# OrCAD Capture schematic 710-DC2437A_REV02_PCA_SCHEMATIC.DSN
size Custom; note: 45V VIN, 500mA LOW NOISE LINEAR REGULATOR WITH; note: PROGRAMMABLE CURRENT LIMIT AND OUTPUT DISCHARGE
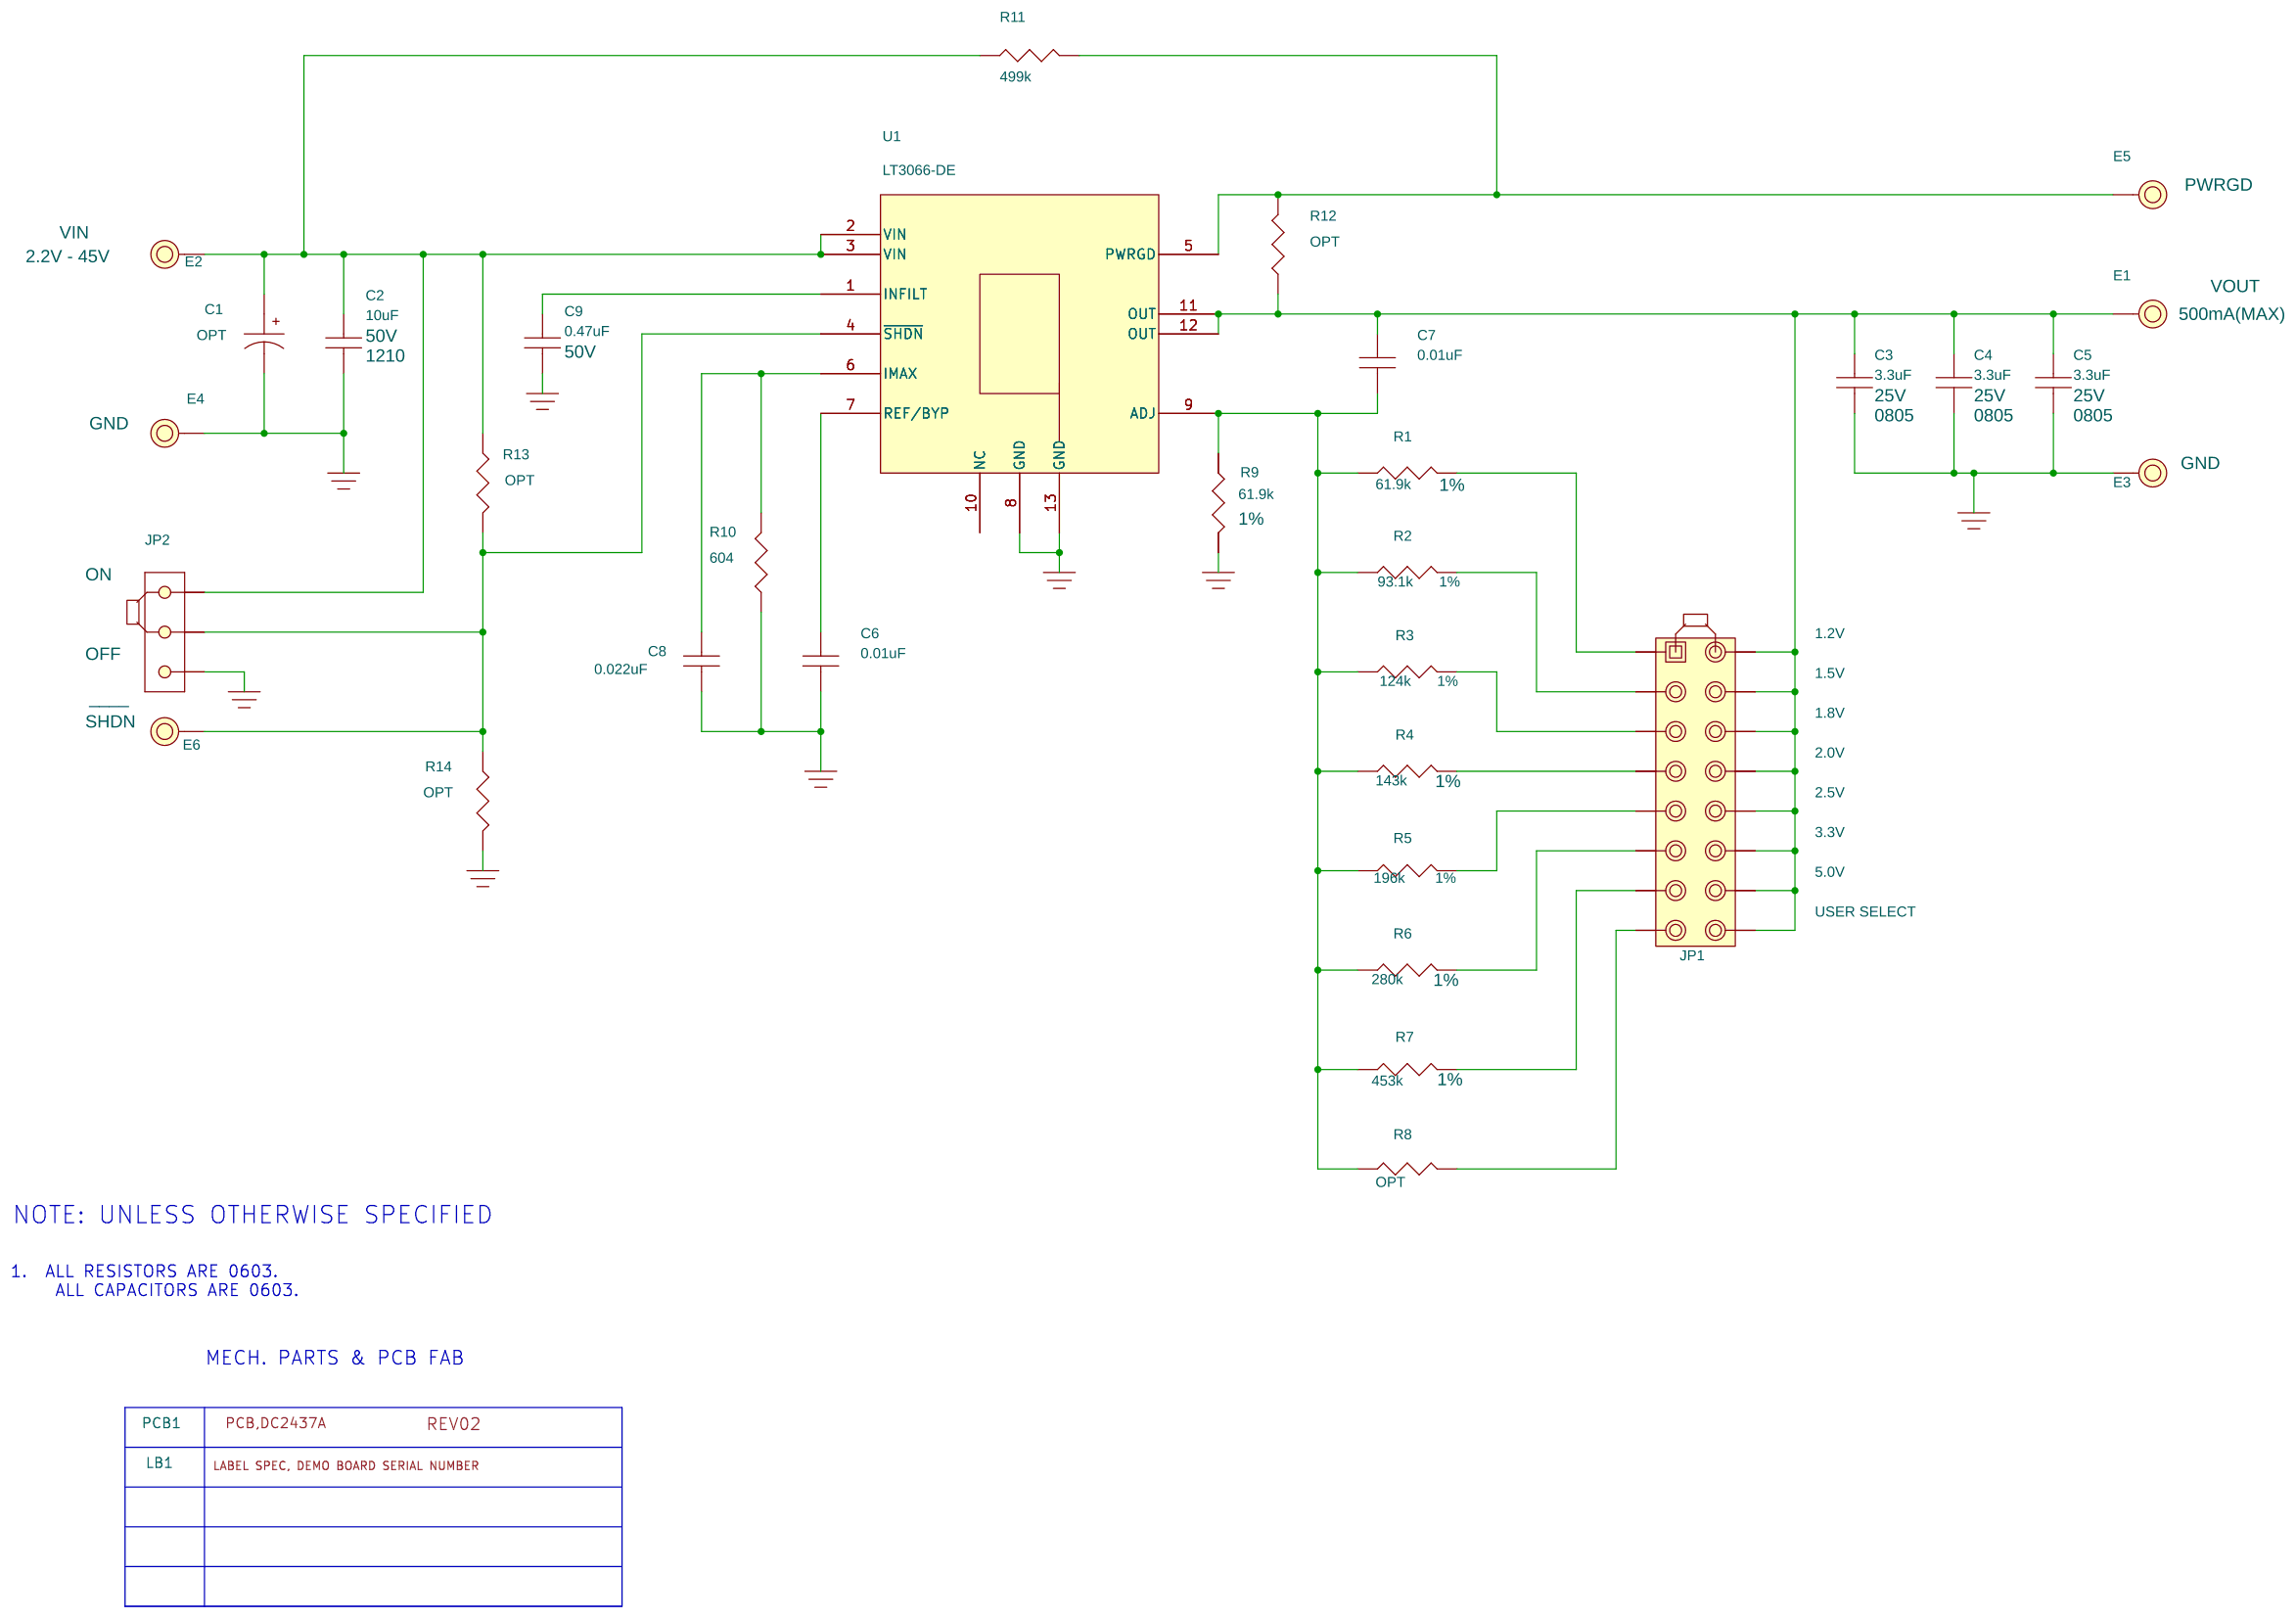
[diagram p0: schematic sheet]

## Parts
C1  OPT  [SUNCON-6.3X5.4]
C2  10uF  [CC1210N]
C3  3.3uF  [CC0805N]
C4  3.3uF  [CC0805N]
C5  3.3uF  [CC0805N]
C6  0.01uF  [CC0603N]
C7  0.01uF  [CC0603N]
C8  0.022uF  [CC0603N]
C9  0.47uF  [CC0603N]
E1  TEST POINT  [MILLMAX2501]
E2  TEST POINT  [MILLMAX2501]
E3  TEST POINT  [MILLMAX2501]
E4  TEST POINT  [MILLMAX2501]
E5  TEST POINT  [MILLMAX2501]
E6  TEST POINT  [MILLMAX2501]
JP1  HEADER  [HD2X8-079]
JP2  HEADER  [JP3X1/079]
LB1  LABEL  [895-0154_REV01]
PCB1  PCB,DC2437A  [MECHANICAL_PART]
R1  61.9k  [CR0603N]
R2  93.1k  [CR0603N]
R3  124k  [CR0603N]
R4  143k  [CR0603N]
R5  196k  [CR0603N]
R6  280k  [CR0603N]
R7  453k  [CR0603N]
R8  OPT  [CR0603N]
R9  61.9k  [CR0603N]
R10  604  [CR0603N]
R11  499k  [CR0603N]
R12  OPT  [CR0603N]
R13  OPT  [CR0603N]
R14  OPT  [CR0603N]
U1  LT3066-DE  [LTC-DE/UE]
XJP1  SHUNT
XJP2  SHUNT

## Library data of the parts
C1 = CAP_P: CAP., OPTION, ALUM. ELECT., SMD; CLASS: DISCRETE; Dielectric Type: ALUM. ELECTROLYTIC; FPLIST: CAP-HVH-6.3X4.5,SUNCON-8X10.2,SUNCON-6.3X5.4; PART_NUMBER: OPT-0011; Package Size: SMT
C2 = CAP: CAP.,10uF,X7R,50V,10%,1210; CLASS: DISCRETE; Dielectric Type: X7R; Manufacturer: MURATA; Manufacturer PN: GRM32ER71H106KA12L; PART_NUMBER: 150-3043; Package Size: 1210; Rated Voltage: 50V; Tolerance: 10%
C3-C5 = CAP: CAP.,3.3uF,X7R,25V,10%,0805; CLASS: DISCRETE; Dielectric Type: X7R; Manufacturer: MURATA; Manufacturer PN: GRM21BR71E335KA73L; PART_NUMBER: 150-0373; Package Size: 0805; Rated Voltage: 25V; Temperature Coefficient: X7R; Tolerance: 10%
C6 C7 = CAP: CAP.,0.01uF,X7R,16V,10%,0603; CLASS: DISCRETE; Dielectric Type: X7R; FPLIST: CC0603N,CC0603L,CC0603M; Manufacturer: AVX; Manufacturer PN: 0603YC103KAT2A; PART_NUMBER: 150-0038; Package Size: 0603; Rated Voltage: 16V; Tolerance: 10%
C8 = CAP: CAP.,0.022uF,X7R,16V,10%,0603; CLASS: DISCRETE; Dielectric Type: X7R; FPLIST: CC0603N,CC0603L,CC0603M; Manufacturer: MURATA; Manufacturer PN: GRM188R71C223KA01D; PART_NUMBER: 150-3074; Package Size: 0603; Rated Voltage: 16V; Tolerance: 10%
C9 = CAP: CAP.,0.47uF,X7R,50V,10%,0603; CLASS: DISCRETE; Dielectric Type: X7R; Manufacturer: TDK; Manufacturer PN: C1608X7R1H474K080AC; PART_NUMBER: 150-0374; Package Size: 0603; Rated Voltage: 50V; Temperature Coefficient: X7R; Tolerance: 10%
E1 = TESTPOINT_.219_MILL-MAX_2501: TEST POINT,TURRET,0.094",MTG. HOLE; CLASS: IO; Manufacturer: MILL-MAX; Manufacturer PN: 2501-2-00-80-00-00-07-0; PART_NUMBER: 260-0003; Part Field 1: VOUT; Part Field 2: 500mA(MAX)
E2 = TESTPOINT_.219_MILL-MAX_2501: TEST POINT,TURRET,0.094",MTG. HOLE; CLASS: IO; Manufacturer: MILL-MAX; Manufacturer PN: 2501-2-00-80-00-00-07-0; PART_NUMBER: 260-0003; Part Field 1: VIN; Part Field 2: 2.2V - 45V
E3 E4 = TESTPOINT_.219_MILL-MAX_2501: TEST POINT,TURRET,0.094",MTG. HOLE; CLASS: IO; Manufacturer: MILL-MAX; Manufacturer PN: 2501-2-00-80-00-00-07-0; PART_NUMBER: 260-0003; Part Field 1: GND; Part Field 2: Part Field 2
E5 = TESTPOINT_.219_MILL-MAX_2501: TEST POINT,TURRET,0.094",MTG. HOLE; CLASS: IO; Manufacturer: MILL-MAX; Manufacturer PN: 2501-2-00-80-00-00-07-0; PART_NUMBER: 260-0003; Part Field 1: PWRGD; Part Field 2: Part Field 2
E6 = TESTPOINT_.219_MILL-MAX_2501: TEST POINT,TURRET,0.094",MTG. HOLE; CLASS: IO; Manufacturer: MILL-MAX; Manufacturer PN: 2501-2-00-80-00-00-07-0; PART_NUMBER: 260-0003; Part Field 1: SHDN; Part Field 2: ____
JP1 = SamtecTMM-108-02-L-D: CONN.,HEADER,MALE,2X8,2mm,THT; 10th Part Field: 1.2V; 11th Part Field: 1.5V; 12th Part Field: 1.8V; 13tht Part Field: 2.0V; 14th Part Field: 2.5V; 15th Part Field: 3.3V; 16th Part Field: 5.0V; 17th Part Field: USER SELECT; CLASS: IO; Manufacturer: SAMTEC; Manufacturer PN: TMM-108-02-L-D; PART_NUMBER: 250-0554
JP2 = 3_PIN_HEADER_.079_SINGLE_ROW_C: CONN.,HEADER,MALE,1X3,2mm,THT; 16th Part Field: ON; 17th Part Field: OFF; CLASS: IO; Manufacturer PN: TMM-103-02-L-S; PART_NUMBER: 250-0422
LB1 = BLANK_LABEL: LABEL SPEC, DEMO BOARD SERIAL NUMBER; Manufacturer: BRADY; Manufacturer PN: THT-96-717-10; PART_NUMBER: 895-0154
PCB1 = BLANK_PCB_PART: BOM Notes: REV02; CLASS: PCB; Manufacturer: MAO BANG; Manufacturer PN: 600-DC2437A; PART_NUMBER: 600-DC2437A
R1 R9 = RES: RES.,61.9k OHMS,1%,1/10W,0603; CLASS: DISCRETE; Manufacturer: VISHAY; Manufacturer PN: CRCW060361K9FKEA; PART_NUMBER: 100-2874; Package Size: 0603; Rated Power: 1/10W; Temperature Coefficient: 100PPM; Tolerance: 1%
R2 = RES: RES.,93.1k OHMS,1%,1/10W,0603; CLASS: DISCRETE; FPLIST: CR0603N,CR0603L,CR0603M; Manufacturer: VISHAY; Manufacturer PN: CRCW060393K1FKEA; PART_NUMBER: 100-2601; Package Size: 0603; Rated Power: 1/10W; Temperature Coefficient: 100ppm/C; Tolerance: 1%
R3 = RES: RES.,124k OHMS,1%,1/10W,0603; CLASS: DISCRETE; FPLIST: CR0603N,CR0603L,CR0603M; Manufacturer: PANASONIC; Manufacturer PN: ERJ3EKF1243V; PART_NUMBER: 100-0224; Package Size: 0603; Rated Power: 1/10W; Temperature Coefficient: 100ppm; Tolerance: 1%
R4 = RES: RES.,143k OHMS,1%,1/10W,0603; CLASS: DISCRETE; Manufacturer: VISHAY; Manufacturer PN: CRCW0603143KFKEA; PART_NUMBER: 100-2875; Package Size: 0603; Rated Power: 1/10W; Temperature Coefficient: +/-100; Tolerance: 1%
R5 = RES: RES.,196k OHMS,1%,1/10W,0603; CLASS: DISCRETE; FPLIST: CR0603N,CR0603L,CR0603M; Manufacturer: VISHAY; Manufacturer PN: CRCW0603196KFKEA; PART_NUMBER: 100-2660; Package Size: 0603; Rated Power: 1/10W; Temperature Coefficient: 100ppm/C; Tolerance: 1%
R6 = RES: RES.,280k OHMS,1%,1/10w,0603; CLASS: DISCRETE; Manufacturer: VISHAY; Manufacturer PN: CRCW0603280KFKEA; PART_NUMBER: 100-2876; Package Size: 0603; Rated Power: 1/10W; Temperature Coefficient: 100PPM; Tolerance: 1%
R7 = RES: RES.,453k OHMS,1%,1/10W,0603; CLASS: DISCRETE; Manufacturer: VISHAY; Manufacturer PN: CRCW0603453KFKEA; PART_NUMBER: 100-2877; Package Size: 0603; Rated Power: 1/10W; Temperature Coefficient: 100PPM; Tolerance: 1%
R8 R12-R14 = RES: RES., OPTION, 0603; CLASS: DISCRETE; Manufacturer: N/A; Manufacturer PN: N/A; PART_NUMBER: 100-2374; Package Size: 0603; Rated Power: N/A; Tolerance: N/A
R10 = RES: RES.,604 OHMS,1%,1/10W,0603; CLASS: DISCRETE; Manufacturer: VISHAY; Manufacturer PN: CRCW0603604RFKEA; PART_NUMBER: 100-2739; Package Size: 0603; Rated Power: 1/10W; Temperature Coefficient: 100ppm; Tolerance: 1%
R11 = RES: RES.,499k OHMS,1%,1/10W,0603; CLASS: DISCRETE; FPLIST: CR0603N,CR0603L,CR0603M; Manufacturer: PANASONIC; Manufacturer PN: ERJ3EKF4993V; PART_NUMBER: 100-0122; Package Size: 0603; Rated Power: 1/10W; Temperature Coefficient: 100ppm/C; Tolerance: 1%
U1 = LT3066-DE: IC,LOW NOISE LINEAR REGULATOR,4X3MM,DFN; CLASS: IC; Manufacturer: LINEAR TECHNOLOGY; Manufacturer PN: LT3066EDE#PBF; PART_NUMBER: LT3066EDE#PBF; Package Size: 4X3 DFN
XJP1 XJP2 = SHUNT_2MM: CONN.,SHUNT,FEMALE,2 POS,2mm; CLASS: IO; Manufacturer PN: 2SN-BK-G; PART_NUMBER: 250-0419

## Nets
GND: C1.2 C2.2 C3.2 C4.2 C5.2 C6.2 C8.2 C9.2 E3.1 E4.1 JP2.3 R9.2 R10.2 R14.1 U1.8(GND) U1.13(GND)
N16893771: C1.1 C2.1 E2.1 JP2.1 R11.1 R13.2 U1.2(VIN) U1.3(VIN)
N16895296: C7.2 R1.1 R2.1 R3.1 R4.1 R5.1 R6.1 R7.1 R8.1 R9.1 U1.9(ADJ)
N16899390: JP1.1 R1.2
N16899440: JP1.3 R2.2
N16899490: JP1.5 R3.2
N16899540: JP1.7 R4.2
N16899590: JP1.9 R5.2
N16899640: JP1.11 R6.2
N16899690: JP1.13 R7.2
N16899740: JP1.15 R8.2
N16899924: C3.1 C4.1 C5.1 C7.1 E1.1 JP1.2 JP1.4 JP1.6 JP1.8 JP1.10 JP1.12 JP1.14 JP1.16 R12.1 U1.11(OUT) U1.12(OUT)
N16932143: E5.1 R11.2 R12.2 U1.5(PWRGD)
N16940179: C8.1 R10.1 U1.6(IMAX)
N16973634: E6.1 JP2.2 R13.1 R14.2 U1.4(~{SHDN})
N16993239: C6.1 U1.7(REF/BYP)
N16993642: C9.1 U1.1(INFILT)

Not connected (* = marked no-connect by the designer): U1 10(NC)

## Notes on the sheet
- NOTE: UNLESS OTHERWISE SPECIFIED
- 1.  ALL RESISTORS ARE 0603.
       ALL CAPACITORS ARE 0603.
- MECH. PARTS & PCB FAB
